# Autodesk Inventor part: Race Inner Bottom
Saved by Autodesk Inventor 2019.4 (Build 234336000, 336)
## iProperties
Created: 2020-05
Part Number: Race Inner Bottom
Material: Generic
Document SubType Name: Modeling
Designer: Administrator
Density: 1 g/cm^3
Appearance: Default
Title: Race Inner Bottom
Author: Administrator
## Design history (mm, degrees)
feature "Race Inner Bottom"
body "Solid1"
